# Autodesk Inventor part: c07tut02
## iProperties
Shininess: 77.0
Length Units: 11269
Angle Units: 11279
Time Units: 11290
Mass Units: 11283
Length Display Precision: 3
Angle Display Precision: 2
Created: 2002-01
Part Number: c07tut02
Document SubType Name: Modeling
Designer: ***
Density: 0.0
Volumn: 0.0
Area: 0.0
PropertySet Name: Model Information
Control State: 0
Master: False
Checked Out: False
Author: ***
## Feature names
1. Extrusion1
2. Extrusion2
3. Extrusion3
4. Chamfer1
